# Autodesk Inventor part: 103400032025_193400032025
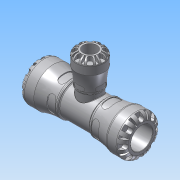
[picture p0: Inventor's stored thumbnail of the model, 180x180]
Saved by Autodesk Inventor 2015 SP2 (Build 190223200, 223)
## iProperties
Created: 2016-12
Part Number: 103400032025_193400032025
Material: PVC-Piping
Description: PLASSON REDUCING TEE 32X25X32 SERIES 1
Document SubType Name: Modeling
Designer: KIM
Mass: 664.223 g
Surface Area: 733.008 cm^2
Volume: 474.445 cm^3
Density: 1.4 g/cm^3
Appearance: Smooth - White
Author: KIM
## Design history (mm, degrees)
derived "1034.ipt"
feature "Solid1::1034.ipt"
tag "TaggingFeature1"
body "Solid1"
other parameters: "d9" = 9, "d11" = 58, "d230" = 47, "d231" = 31.25, "d232" = 7.875, "d1" = 22.68, "d2" = 32, "d4" = 58, "d8" = 49.3, "d13" = 7.2, "d14" = 7.2, "d15" = 0, "d17" = 360 deg, "d19" = 8 deg, "d20" = 0.64, "d21" = 0.64, "d22" = 8 deg, "d24" = 0, "d26" = 360 deg, "d33" = 5.8, "d43" = 45.24, "d51" = 0.58, "d54" = 11.2, "d55" = 7.04, "d57" = 14.112, "d58" = 0, "d74" = 0, "d77" = 2.66667, "d78" = 54, "d79" = 45.24, "d80" = 152, "d82" = 0.64, "d115" = 360 deg, "d139" = 7.2, "d140" = 0, "d142" = 360 deg, "d207" = 90 deg, "d209" = 20.58, "d210" = 25, "d211" = 31.25, "d212" = 47, "d213" = 39.95, "d215" = 36.66, "d216" = 2.08333, "d217" = 49, "d225" = 81, "d226" = 49, "d228" = 9.52, "d229" = 6.3, "d233" = 6.3, "d234" = 0, "d236" = 360 deg, "d238" = 8 deg, "d239" = 8 deg, "d240" = 0.64, "d241" = 0.64, "d243" = 0, "d245" = 360 deg, "d247" = 1.16, "d248" = 3.24, "d249" = 2.94, "d250" = 7.4375, "d252" = 8.75, "d253" = 5.75, "d254" = 14.112, "d255" = 0, "d257" = 360 deg, "d259" = 0.64, "d261" = 0, "d262" = 1.16, "d264" = 0, "d266" = 0, "d267" = 0.58, "d_" = 32, "E_" = 58, "l_" = 54, "A_" = 81, "H_" = 152, "d_1" = 25, "E_1" = 47, "l_1" = 49
